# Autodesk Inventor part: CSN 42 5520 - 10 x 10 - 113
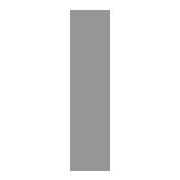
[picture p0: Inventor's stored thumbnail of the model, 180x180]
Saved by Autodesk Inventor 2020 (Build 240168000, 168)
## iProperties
IsCustomPart: 1
Created: 2019-01
Part Number: CSN 42 5520 - 10 x 10 - 113
Material: Ocel, měkká
Description: Tyč
Document SubType Name: Modeling
Standard: CSN 42 5520
Designer: doma
Standards Organization: CSN
Language: cs-CZ
Size Designation: 10 x 10 - 113
Categories: <MemberInstance><Categories><Category DisplayName="Konstrukční profily" InternalName="089c4875-fa83-4c05-b084-43b9cc11f5ed" Mnemonic="GRDR"><CategoryParameter D
Stock Number: 10 x 10
Density: 7.85 g/cm^3
Appearance: Pololeštěná
Mass: 85.8496 g
Surface Area: 45.8274 cm^2
Volume: 10.9363 cm^3
G_L: 113,000 mm
Author: doma
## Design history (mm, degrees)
node "Počáteční rovina"
node "Koncová rovina"
sketch "Náčrt"
  geometry: L1 (5, -5)-(-5, -5); L2 (-5, -5)-(-5, 5); L3 (-5, 5)-(5, 5); L4 (5, 5)-(5, -5); L5 (-6, 0)-(8, 0); L6 (0, -30)-(0, 40); L7 (0, 54)-(0, -44) reference; L8 (-9.2, 0)-(13.2, 0) reference
  constraints: 12 end point, 2 collinear, 2 parallel, 1 horizontal, 1 perpendicular
  dimensions: "d0" = 10 distance between parallel lines of L3 L1 (= G_W); "d1" = 10 distance between parallel lines of L4 L2 (= G_H); "d4" = 5 distance between parallel lines of L6 L4 (= 0.5 x d1); "d5" = 5 distance between parallel lines of L5 L3 (= 0.5 x d0)
extrude "Těleso" new body sketch "Náčrt" stored distance "d2" = 113 (= G_L); taper "d3" = 0 deg
node "Driven Length"
  sketch "Sketch3"
    geometry: L1 (0, 0)-(10, 0) reference
    constraints: 2 end point, 1 horizontal
  workplane "Work Plane3"
  sketch "Sketch4"
    geometry: L1 (-2, 0)-(12, 0) reference; L2 (-2, 113)-(12, 113) reference
    dimensions: "d9" = 113 distance between parallel lines of L1 L2 (derived)
sketch "Náčrt6"
  geometry: L1 (0, 3)-(7, 10) reference; L2 (113.637, 0.099)-(280.686, 124.03) reference; L3 (286.018, 140.437)-(110.199, 10) reference; L4 (113, 10)-(0, 10) reference; L5 (113.637, 0.099)-(111.976, -1.133); L6 (113, 0)-(0, 0) reference; L7 (113, 0)-(114.851, 0); L8 (113.503, 0)-(110.199, 10); L9 (113.503, 0)-(118.183, -2.08); L10 (118.183, -2.08)-(114.851, 17.516); L11 (114.851, 17.516)-(110.199, 10); L12 (0, 3)-(-6.327, 3); L13 (-6.327, 3)-(-7.638, 15.55); L14 (-7.638, 15.55)-(7.87, 17.17); L15 (7.87, 17.17)-(7, 10); 1 further point
  constraints: 20 end point, 4 point on line, 2 horizontal, 1 perpendicular
extrude "Vysunutí2" cut sketch "Náčrt6" extent not by distance; stored distance "d10" = 0; taper "d11" = 0 deg
chamfer "Zkosení1" distance "d12" = 2; stored, may be unused: second distance "d13" = 2, angle "d14" = 45 deg
body "Solid1"
node "Referenční1"
node "Referenční2"
node "Referenční3"
other parameters: "G_W" = 10 [user parameter; used in 1 equation term], "G_H" = 10 [user parameter; used in 1 equation term], "G_L" = 113 (= d9) [user parameter; used in 1 equation term], "G_OFFSET_START" = 0 [user parameter; used in 1 equation term], "G_OFFSET_END" = 0 [user parameter; used in 1 equation term], "d6" = 0 (computed from G_OFFSET_START), "d7" = 113 (= G_OFFSET_END + B_L), "B_L" = 113 [user parameter; used in 1 equation term], "d8" = 90 deg
